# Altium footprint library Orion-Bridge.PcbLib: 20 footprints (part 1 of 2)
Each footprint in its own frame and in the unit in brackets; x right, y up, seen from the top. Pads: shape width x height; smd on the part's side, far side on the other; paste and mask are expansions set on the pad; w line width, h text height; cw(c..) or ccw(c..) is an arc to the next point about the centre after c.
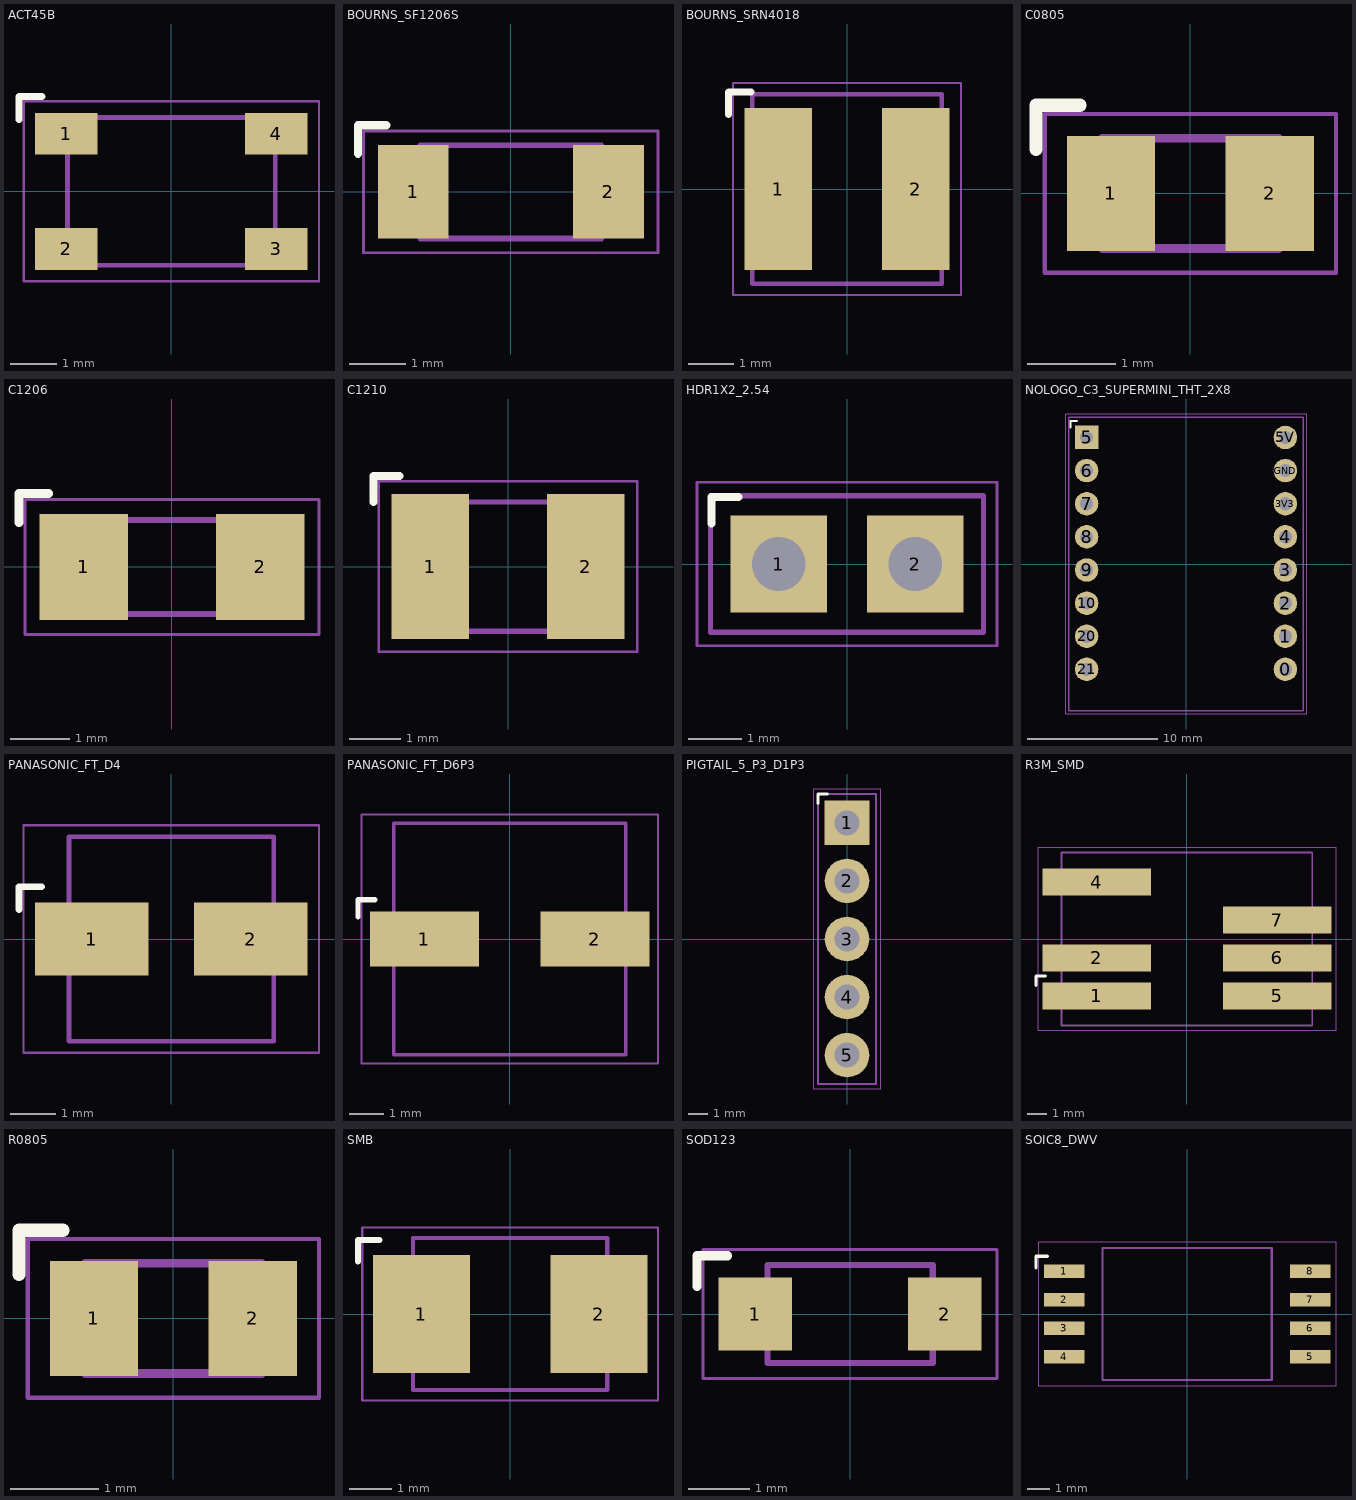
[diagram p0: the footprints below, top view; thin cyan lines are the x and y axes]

## ACT45B [mm] "TDK ACT45B recommended lands; windings 1-4 and 2-3"
height 2.8
pads (4):
  rect 1.35x0.9 smd: 1(-2.275,1.25) 2(-2.275,-1.25) 3(2.275,-1.25) 4(2.275,1.25)
Top Overlay:
  lines w0.15: -3.3,1.55 -3.3,2.05 -2.8,2.05
Component bodies:
  lines w0.1: -2.25,-1.6 2.25,-1.6 2.25,1.6 -2.25,1.6 -2.25,-1.6
Courtyards:
  lines w0.05: -3.2,-1.95 3.2,-1.95 3.2,1.95 -3.2,1.95 -3.2,-1.95
3D body: height 2.8, standoff 0.12, extent -2.25,-1.6 2.25,1.6
3D body: height 0.28, standoff 0.02, extent -2.575,0.935 -1.9,1.565
3D body: height 0.28, standoff 0.02, extent -2.575,-1.565 -1.9,-0.935
3D body: height 0.28, standoff 0.02, extent 1.9,-1.565 2.575,-0.935
3D body: height 0.28, standoff 0.02, extent 1.9,0.935 2.575,1.565

## BOURNS_SF1206S [mm] "Bourns SF-1206S recommended land pattern: total X span 4.7, inner gap 2.2, pad Y 1.65; maximum body envelope. No polarity."
height 0.7
pads (2):
  rect 1.25x1.65 smd: 1(-1.725,0) 2(1.725,0)
Top Overlay:
  lines w0.15: -2.7,0.675 -2.7,1.175 -2.2,1.175
Component bodies:
  lines w0.1: -1.6,-0.825 1.6,-0.825 1.6,0.825 -1.6,0.825 -1.6,-0.825
Courtyards:
  lines w0.05: -2.6,-1.075 2.6,-1.075 2.6,1.075 -2.6,1.075 -2.6,-1.075
3D body: height 0.7, standoff 0.15, extent -1.6,-0.825 1.6,0.825
3D body: height 0.72, standoff 0.02, extent -1.6,-0.835 -1.088,0.835
3D body: height 0.72, standoff 0.02, extent 1.088,-0.835 1.6,0.835

## BOURNS_SRN4018 [mm] "Bourns SRN4018 recommended land pattern: 4.55 total X, two 1.5 x 3.6 pads. Maximum body envelope 4.2 x 4.2. No polarity."
height 1.8
pads (2):
  rect 1.5x3.6 smd: 1(-1.525,0) 2(1.525,0)
Top Overlay:
  lines w0.15: -2.625,1.65 -2.625,2.15 -2.125,2.15
Component bodies:
  lines w0.1: -2.1,-2.1 2.1,-2.1 2.1,2.1 -2.1,2.1 -2.1,-2.1
Courtyards:
  lines w0.05: -2.525,-2.35 2.525,-2.35 2.525,2.35 -2.525,2.35 -2.525,-2.35
3D body: height 1.8, standoff 0.12, extent -2.1,-2.1 2.1,2.1
3D body: height 0.28, standoff 0.02, extent -1.937,-1.17 -1.112,1.17
3D body: height 0.28, standoff 0.02, extent 1.112,-1.17 1.937,1.17

## C0805 [mm] "0805 generic capacitor lands; MPN review"
height 1.2
pads (2):
  rect 1x1.3 smd: 1(-0.9,0) 2(0.9,0)
Top Overlay:
  lines w0.15: -1.75,0.5 -1.75,1 -1.25,1
Component bodies:
  lines w0.1: -1,-0.625 1,-0.625 1,0.625 -1,0.625 -1,-0.625
Courtyards:
  lines w0.05: -1.65,-0.9 1.65,-0.9 1.65,0.9 -1.65,0.9 -1.65,-0.9
3D body: height 1.2, standoff 0.12, extent -1,-0.625 1,0.625
3D body: height 1.22, standoff 0.02, extent -1,-0.635 -0.6,0.635
3D body: height 1.22, standoff 0.02, extent 0.6,-0.635 1,0.635

## C1206 [mm] "1206 generic capacitor lands; effective capacitance review"
height 1.6
pads (2):
  rect 1.5x1.8 smd: 1(-1.5,0) 2(1.5,0)
Top Overlay:
  lines w0.15: -2.6,0.75 -2.6,1.25 -2.1,1.25
Component bodies:
  lines w0.1: -1.6,-0.8 1.6,-0.8 1.6,0.8 -1.6,0.8 -1.6,-0.8
Courtyards:
  lines w0.05: -2.5,-1.15 2.5,-1.15 2.5,1.15 -2.5,1.15 -2.5,-1.15
3D body: height 1.6, standoff 0.12, extent -1.6,-0.8 1.6,0.8
3D body: height 1.63, standoff 0.02, extent -1.6,-0.81 -1.2,0.81
3D body: height 1.63, standoff 0.02, extent 1.2,-0.81 1.6,0.81

## C1210 [mm] "1210 generic capacitor lands; effective capacitance review"
height 2.5
pads (2):
  rect 1.5x2.8 smd: 1(-1.5,0) 2(1.5,0)
Top Overlay:
  lines w0.15: -2.6,1.25 -2.6,1.75 -2.1,1.75
Component bodies:
  lines w0.1: -1.6,-1.25 1.6,-1.25 1.6,1.25 -1.6,1.25 -1.6,-1.25
Courtyards:
  lines w0.05: -2.5,-1.65 2.5,-1.65 2.5,1.65 -2.5,1.65 -2.5,-1.65
3D body: height 2.5, standoff 0.12, extent -1.6,-1.25 1.6,1.25
3D body: height 2.52, standoff 0.02, extent -1.6,-1.26 -1.2,1.26
3D body: height 2.52, standoff 0.02, extent 1.2,-1.26 1.6,1.26

## HDR1X2_2.54 [mm] "TBD 2.54 mm service jumper; open BEFORE connecting USB"
height 6
pads (2):
  rect 1.8x1.8 hole 1: 1(-1.27,0) 2(1.27,0)
Top Overlay:
  lines w0.15: -2.52,0.75 -2.52,1.25 -2.02,1.25
Component bodies:
  lines w0.1: -2.54,-1.27 2.54,-1.27 2.54,1.27 -2.54,1.27 -2.54,-1.27
Courtyards:
  lines w0.05: -2.79,-1.52 2.79,-1.52 2.79,1.52 -2.79,1.52 -2.79,-1.52
3D body: height 2.6, standoff 0.1, extent -2.54,-1.27 2.54,1.27
3D body: height 6, standoff -2.5, extent -1.59,-0.32 -0.95,0.32
3D body: height 6, standoff -2.5, extent 0.95,-0.32 1.59,0.32
3D body: height 6.8, standoff 3.2, extent -2.55,-1.25 2.55,1.25
3D body: height 7.2, standoff 6.8, extent -2.1,-1.15 2.1,1.15

## NOLOGO_C3_SUPERMINI_THT_2X8 [mm] "Nologo 16-pin carrier interface; 15.24 mm rows / 2.54 mm pitch. Local assembly-model height 7.2 mm assumes 3.1 mm carrier-to-module underside, 1.0 mm module PCB and 3.1 mm USB body. This is not a verified manufacturer maximum; actual header seating and module revision must be checked."
height 7.2
pads (16):
  round 1.8 hole 1: 0(7.62,-8.079) 1(7.62,-5.539) 2(7.62,-2.999) 3(7.62,-0.459) 3V3(7.62,4.621) 4(7.62,2.081) 5V(7.62,9.701) 6(-7.62,7.161) 7(-7.62,4.621) 8(-7.62,2.081) 9(-7.62,-0.459) 10(-7.62,-2.999) 20(-7.62,-5.539) 21(-7.62,-8.079) GND(7.62,7.161)
  rect 1.8x1.8 hole 1: 5(-7.62,9.701)
Top Overlay:
  lines w0.15: -8.87,10.451 -8.87,10.951 -8.37,10.951
Component bodies:
  lines w0.1: -9,-11.25 9,-11.25 9,11.25 -9,11.25 -9,-11.25
Courtyards:
  lines w0.05: -9.25,-11.5 9.25,-11.5 9.25,11.5 -9.25,11.5 -9.25,-11.5
3D body: height 3.1, standoff 0.1, extent -8.89,-9.349 -6.35,10.971
3D body: height 3.1, standoff 0.1, extent 6.35,-9.349 8.89,10.971
3D body: height 4.5, standoff -2.5, extent -7.94,9.381 -7.3,10.021
3D body: height 4.5, standoff -2.5, extent -7.94,6.841 -7.3,7.481
3D body: height 4.5, standoff -2.5, extent -7.94,4.301 -7.3,4.941
3D body: height 4.5, standoff -2.5, extent -7.94,1.761 -7.3,2.401
3D body: height 4.5, standoff -2.5, extent -7.94,-0.779 -7.3,-0.139
3D body: height 4.5, standoff -2.5, extent -7.94,-3.319 -7.3,-2.679
3D body: height 4.5, standoff -2.5, extent -7.94,-5.859 -7.3,-5.219
3D body: height 4.5, standoff -2.5, extent -7.94,-8.399 -7.3,-7.759
3D body: height 4.5, standoff -2.5, extent 7.3,9.381 7.94,10.021
3D body: height 4.5, standoff -2.5, extent 7.3,6.841 7.94,7.481
3D body: height 4.5, standoff -2.5, extent 7.3,4.301 7.94,4.941
3D body: height 4.5, standoff -2.5, extent 7.3,1.761 7.94,2.401
3D body: height 4.5, standoff -2.5, extent 7.3,-0.779 7.94,-0.139
3D body: height 4.5, standoff -2.5, extent 7.3,-3.319 7.94,-2.679
3D body: height 4.5, standoff -2.5, extent 7.3,-5.859 7.94,-5.219
3D body: height 4.5, standoff -2.5, extent 7.3,-8.399 7.94,-7.759
3D body: height 4.1, standoff 3.1, extent -9,-11.25 9,11.25
3D body: height 5.05, standoff 4.1, extent -2.5,-4 2.5,1
3D body: height 7.2, standoff 6.85, extent -4.4,4.55 4.4,11.75
3D body: height 4.45, standoff 4.1, extent -4.4,4.55 4.4,11.75
3D body: height 6.85, standoff 4.45, extent -4.4,4.55 -4.1,11.75
3D body: height 6.85, standoff 4.45, extent 4.1,4.55 4.4,11.75
3D body: height 5.85, standoff 5.5, extent -3.25,7.85 3.25,11.45
3D body: height 5.15, standoff 4.1, extent -1.6,-10.85 1.6,-9.25
3D body: height 4.7, standoff 4.1, extent -7.45,0.65 -4.15,3.95
3D body: height 5.2, standoff 4.7, extent -6.6,1.5 -5,3.1
3D body: height 4.7, standoff 4.1, extent 4.15,0.65 7.45,3.95
3D body: height 5.2, standoff 4.7, extent 5,1.5 6.6,3.1

## PANASONIC_FT_D4 [mm] "Panasonic FT standard size B land pattern: a=1.0 gap, b=2.5 pad length, c=1.6 pad width. Body is maximum plastic-base envelope; can nominal diameter 4.0. Pin 1 positive, pin 2 negative."
height 6.1
pads (2):
  rect 2.5x1.6 smd: 1(-1.75,0) 2(1.75,0)
Top Overlay:
  lines w0.15: -3.35,0.65 -3.35,1.15 -2.85,1.15
Component bodies:
  lines w0.1: -2.25,-2.25 2.25,-2.25 2.25,2.25 -2.25,2.25 -2.25,-2.25
Courtyards:
  lines w0.05: -3.25,-2.5 3.25,-2.5 3.25,2.5 -3.25,2.5 -3.25,-2.5
3D body: height 5.8, standoff 0.6, extent -2,-2 2,2
3D body: height 6.1, standoff 5.8, extent -1.75,-1.75 1.75,1.75
3D body: height 6.11, standoff 6.1, extent -1.1,-0.04 1.1,0.04
3D body: height 6.11, standoff 6.1, extent -0.04,-1.1 0.04,1.1
3D body: height 5.6, standoff 0.7, extent 1.7,-0.6 2,0.6
3D body: height 0.65, standoff 0.05, extent -2.15,-2.15 2.15,2.15
3D body: height 0.25, standoff 0.02, extent -2.688,-0.48 -0.813,0.48
3D body: height 0.25, standoff 0.02, extent 0.813,-0.48 2.688,0.48

## PANASONIC_FT_D6P3 [mm] "Panasonic FT standard size D land pattern: a=1.8 gap, b=3.2 pad length, c=1.6 pad width. Body is maximum plastic-base envelope; can nominal diameter 6.3. Pin 1 positive, pin 2 negative."
height 6.1
pads (2):
  rect 3.2x1.6 smd: 1(-2.5,0) 2(2.5,0)
Top Overlay:
  lines w0.15: -4.45,0.65 -4.45,1.15 -3.95,1.15
Component bodies:
  lines w0.1: -3.4,-3.4 3.4,-3.4 3.4,3.4 -3.4,3.4 -3.4,-3.4
Courtyards:
  lines w0.05: -4.35,-3.65 4.35,-3.65 4.35,3.65 -4.35,3.65 -4.35,-3.65
3D body: height 5.8, standoff 0.6, extent -3.15,-3.15 3.15,3.15
3D body: height 6.1, standoff 5.8, extent -2.9,-2.9 2.9,2.9
3D body: height 6.11, standoff 6.1, extent -1.733,-0.04 1.733,0.04
3D body: height 6.11, standoff 6.1, extent -0.04,-1.733 0.04,1.733
3D body: height 5.6, standoff 0.7, extent 2.85,-0.945 3.15,0.945
3D body: height 0.65, standoff 0.05, extent -3.3,-3.3 3.3,3.3
3D body: height 0.25, standoff 0.02, extent -3.7,-0.48 -1.3,0.48
3D body: height 0.25, standoff 0.02, extent 1.3,-0.48 3.7,0.48

## PIGTAIL_5_P3_D1P3 [mm] "Designed carrier wire-solder interface, 3.0 pitch, 1.3 finished-hole target, 0.5 radial annulus. Pin numbering is logical NMEA: 1 shield, 2 NET-S, 3 NET-C, 4 CAN-H, 5 CAN-L. Cable and strain relief still require a physical selection."
height 3
pads (5):
  rect 2.3x2.3 hole 1.3: 1(0,6)
  round 2.3 hole 1.3: 2(0,3) 3(0,0) 4(0,-3) 5(0,-6)
Top Overlay:
  lines w0.15: -1.5,7 -1.5,7.5 -1,7.5
Component bodies:
  lines w0.1: -1.5,-7.5 1.5,-7.5 1.5,7.5 -1.5,7.5 -1.5,-7.5
Courtyards:
  lines w0.05: -1.75,-7.75 1.75,-7.75 1.75,7.75 -1.75,7.75 -1.75,-7.75
3D body: height 1.8, standoff -1.8, extent -0.35,5.65 0.35,6.35
3D body: height 6, standoff 1.8, extent -0.8,5.2 0.8,6.8
3D body: height 1.8, standoff -1.8, extent -0.35,2.65 0.35,3.35
3D body: height 6, standoff 1.8, extent -0.8,2.2 0.8,3.8
3D body: height 1.8, standoff -1.8, extent -0.35,-0.35 0.35,0.35
3D body: height 6, standoff 1.8, extent -0.8,-0.8 0.8,0.8
3D body: height 1.8, standoff -1.8, extent -0.35,-3.35 0.35,-2.65
3D body: height 6, standoff 1.8, extent -0.8,-3.8 0.8,-2.2
3D body: height 1.8, standoff -1.8, extent -0.35,-6.35 0.35,-5.65
3D body: height 6, standoff 1.8, extent -0.8,-6.8 0.8,-5.2

## R3M_SMD [mm] "RECOM recommended R3M SMD land pattern; 3.8 mm inner pad gap"
height 10.2
pads (6):
  rect 5.7x1.4 smd: 1(-4.75,-3) 2(-4.75,-1) 4(-4.75,3) 5(4.75,-3) 6(4.75,-1) 7(4.75,1)
Top Overlay:
  lines w0.15: -7.95,-2.45 -7.95,-1.95 -7.45,-1.95
Component bodies:
  lines w0.1: -6.6,-4.55 6.6,-4.55 6.6,4.55 -6.6,4.55 -6.6,-4.55
Courtyards:
  lines w0.05: -7.85,-4.8 7.85,-4.8 7.85,4.8 -7.85,4.8 -7.85,-4.8
3D body: height 10.2, standoff 0.3, extent -6.6,-4.55 6.6,4.55
3D body: height 10.23, standoff 10.2, extent -5.28,-2.73 5.28,2.73
3D body: height 0.3, standoff 0.02, extent -7.458,-3.42 -2.043,-2.58
3D body: height 0.3, standoff 0.02, extent -7.458,-1.42 -2.043,-0.58
3D body: height 0.3, standoff 0.02, extent -7.458,2.58 -2.043,3.42
3D body: height 0.3, standoff 0.02, extent 2.043,-3.42 7.458,-2.58
3D body: height 0.3, standoff 0.02, extent 2.043,-1.42 7.458,-0.58
3D body: height 0.3, standoff 0.02, extent 2.043,0.58 7.458,1.42

## R0805 [mm] "0805 generic resistor lands; MPN review"
height 0.6
pads (2):
  rect 1x1.3 smd: 1(-0.9,0) 2(0.9,0)
Top Overlay:
  lines w0.15: -1.75,0.5 -1.75,1 -1.25,1
Component bodies:
  lines w0.1: -1,-0.625 1,-0.625 1,0.625 -1,0.625 -1,-0.625
Courtyards:
  lines w0.05: -1.65,-0.9 1.65,-0.9 1.65,0.9 -1.65,0.9 -1.65,-0.9
3D body: height 0.6, standoff 0.12, extent -1,-0.625 1,0.625
3D body: height 0.63, standoff 0.02, extent -1,-0.635 -0.6,0.635
3D body: height 0.63, standoff 0.02, extent 0.6,-0.635 1,0.635

## SMB [mm] "DO-214AA SMB generic lands; 1=cathode 2=anode; verify vendor"
height 2.5
pads (2):
  rect 2.3x2.8 smd: 1(-2.1,0) 2(2.1,0)
Top Overlay:
  lines w0.15: -3.6,1.25 -3.6,1.75 -3.1,1.75
Component bodies:
  lines w0.1: -2.3,-1.8 2.3,-1.8 2.3,1.8 -2.3,1.8 -2.3,-1.8
Courtyards:
  lines w0.05: -3.5,-2.05 3.5,-2.05 3.5,2.05 -3.5,2.05 -3.5,-2.05
3D body: height 2.5, standoff 0.12, extent -2.3,-1.8 2.3,1.8
3D body: height 0.28, standoff 0.02, extent -2.732,-0.91 -1.468,0.91
3D body: height 0.28, standoff 0.02, extent 1.468,-0.91 2.732,0.91
3D body: height 2.51, standoff 2.5, extent -1.597,-1.674 -1.347,1.674

## SOD123 [mm] "SOD-123 generic lands; 1=cathode 2=anode; verify vendor"
height 1.2
pads (2):
  rect 1.2x1.2 smd: 1(-1.55,0) 2(1.55,0)
Top Overlay:
  lines w0.15: -2.5,0.45 -2.5,0.95 -2,0.95
Component bodies:
  lines w0.1: -1.35,-0.8 1.35,-0.8 1.35,0.8 -1.35,0.8 -1.35,-0.8
Courtyards:
  lines w0.05: -2.4,-1.05 2.4,-1.05 2.4,1.05 -2.4,1.05 -2.4,-1.05
3D body: height 1.2, standoff 0.12, extent -1.35,-0.8 1.35,0.8
3D body: height 0.28, standoff 0.02, extent -1.85,-0.42 -1,0.42
3D body: height 0.28, standoff 0.02, extent 1,-0.42 1.85,0.42
3D body: height 1.21, standoff 1.2, extent -0.989,-0.744 -0.739,0.744

## SOIC8_DWV [mm] "TI DWV0008A manufacturer land pattern; pin 1 upper left"
height 2.8
pads (8):
  rect 1.8x0.6 smd: 1(-5.45,1.905) 2(-5.45,0.635) 3(-5.45,-0.635) 4(-5.45,-1.905) 5(5.45,-1.905) 6(5.45,-0.635) 7(5.45,0.635) 8(5.45,1.905)
Top Overlay:
  lines w0.15: -6.7,2.055 -6.7,2.555 -6.2,2.555
Component bodies:
  lines w0.1: -3.75,-2.925 3.75,-2.925 3.75,2.925 -3.75,2.925 -3.75,-2.925
Courtyards:
  lines w0.05: -6.6,-3.175 6.6,-3.175 6.6,3.175 -6.6,3.175 -6.6,-3.175
3D body: height 2.8, standoff 0.12, extent -3.75,-2.925 3.75,2.925
3D body: height 0.28, standoff 0.02, extent -5.75,1.695 -3.4,2.115
3D body: height 0.28, standoff 0.02, extent -5.75,0.425 -3.4,0.845
3D body: height 0.28, standoff 0.02, extent -5.75,-0.845 -3.4,-0.425
3D body: height 0.28, standoff 0.02, extent -5.75,-2.115 -3.4,-1.695
3D body: height 0.28, standoff 0.02, extent 3.4,-2.115 5.75,-1.695
3D body: height 0.28, standoff 0.02, extent 3.4,-0.845 5.75,-0.425
3D body: height 0.28, standoff 0.02, extent 3.4,0.425 5.75,0.845
3D body: height 0.28, standoff 0.02, extent 3.4,1.695 5.75,2.115
3D body: height 2.82, standoff 2.8, extent -2.56,1.478 -2.24,1.798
